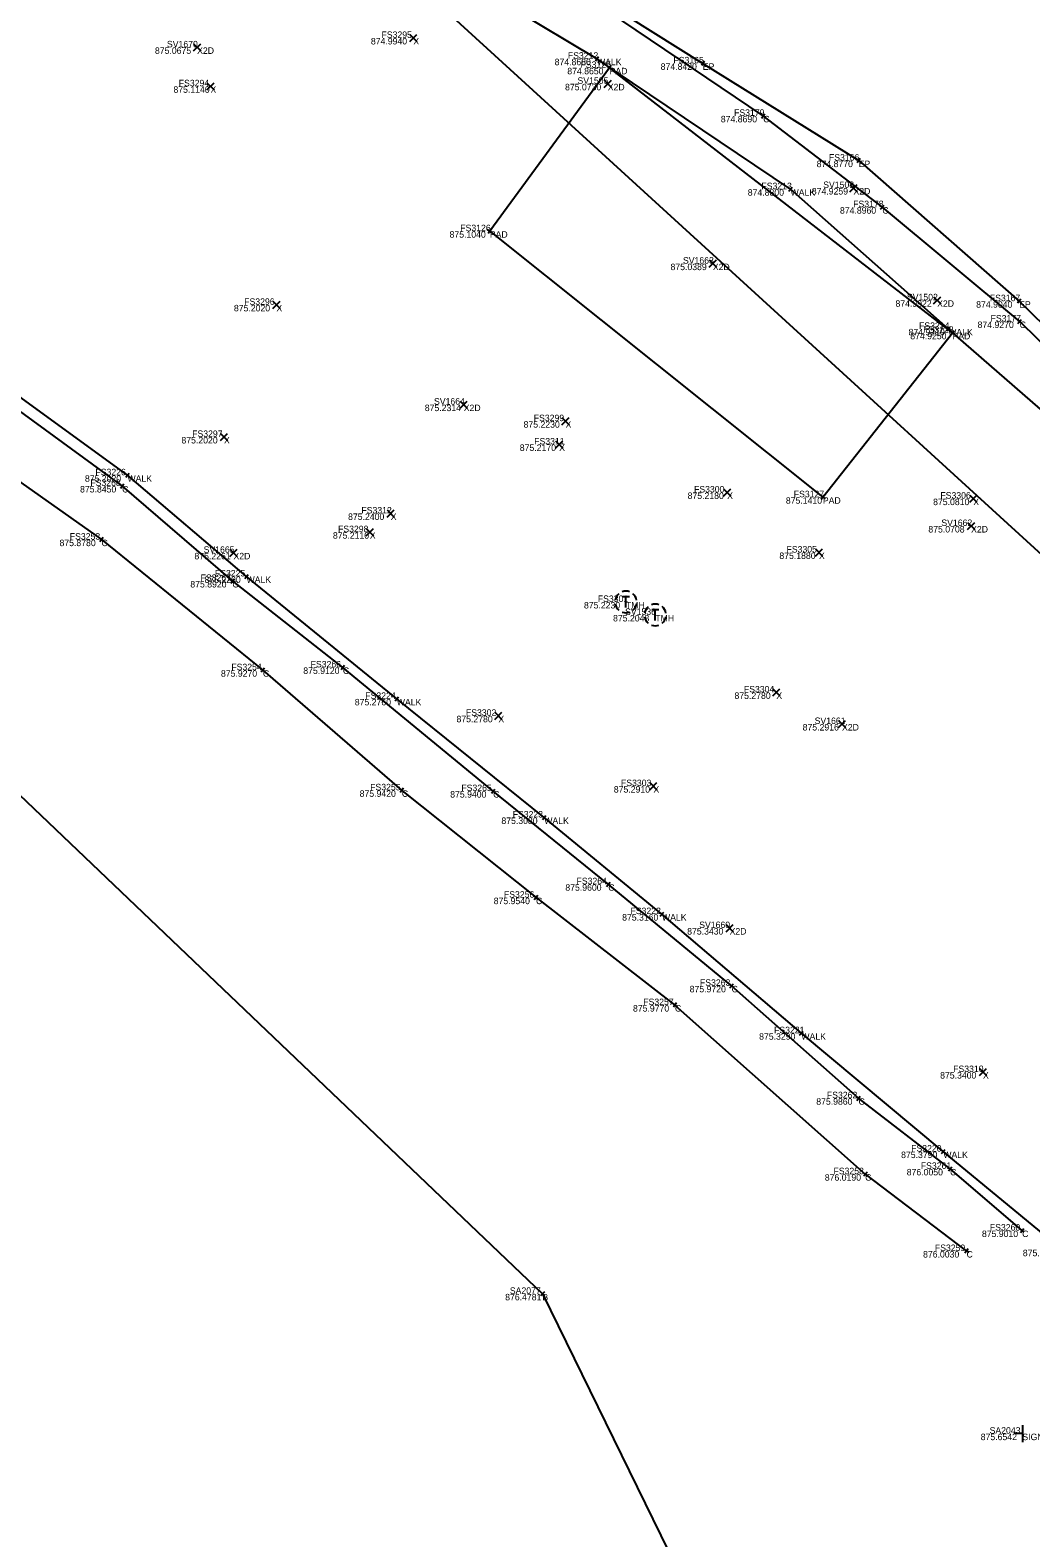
# Model space of a CAD drawing. Extents: x 1479481 to 1575806, y 316056 to 379927.
# Drawn here: x 1480179.92 to 1480189.17, y 379370.17 to 379384.1 of the extents above; entities that cross this region are included whole.
import ezdxf

# ---------------------------------------------------------------- set-up
doc = ezdxf.new("R2010")
doc.units = 0
for name, color, linetype in [('Default', 7, 'Continuous'), ('PV_X_Curb', 7, 'Continuous'), ('PV_X_EOP', 7, 'Continuous'), ('PV_X_Walk', 7, 'Continuous'), ('RD_X_Concrete_Pad', 7, 'Continuous'), ('SN_X_Public', 7, 'Continuous'), ('SV_X_Break_Lines', 7, 'Continuous'), ('SV_X_Random_Point', 7, 'Continuous'), ('SV_X_Shot_Marker', 7, 'Continuous'), ('SV_X_Text_Comment', 7, 'Continuous'), ('SV_X_Text_Elevation', 7, 'Continuous'), ('SV_X_Text_Name', 7, 'Continuous'), ('UT_X_Telecom_Cells', 7, 'Continuous'), ('UT_X_Water', 7, 'Continuous')]:
    doc.layers.add(name, color=color, linetype=linetype)

msp = doc.modelspace()

# ---------------------------------------------------------------- linework, layer by layer
at = {"layer": 'Default'}
msp.add_lwpolyline([(1480189.091, 379371.129), (1480189.091, 379371.129)], dxfattribs=at)
at = {"layer": 'PV_X_Curb'}
for points in [[(1480200.436, 379370.31), (1480193.202, 379376.933), (1480192.331, 379377.692), (1480191.145, 379378.864), (1480189.945, 379379.999), (1480188.405, 379381.34), (1480186.948, 379382.631), (1480185.159, 379383.837), (1480183.612, 379384.764), (1480182.42, 379385.277), (1480180.94, 379385.773), (1480179.383, 379386.306), (1480178.708, 379386.55), (1480176.982, 379386.784), (1480175.084, 379387.087), (1480173.11, 379387.257), (1480172.166, 379387.208), (1480170.557, 379387.026), (1480168.815, 379386.8), (1480167.667, 379386.487), (1480166.614, 379386.24), (1480165.014, 379385.711), (1480163.297, 379385.035), (1480160.165, 379383.332)], [(1480200.731, 379370.664), (1480194.552, 379376.232), (1480193.456, 379377.305), (1480192.298, 379378.387), (1480191.096, 379379.488), (1480190.065, 379380.428), (1480189.066, 379381.408), (1480187.797, 379382.465), (1480186.696, 379383.309), (1480185.265, 379384.273), (1480183.824, 379385.018), (1480182.233, 379385.673), (1480180.762, 379386.381), (1480178.806, 379386.86)], [(1480189.089, 379373.006), (1480188.423, 379373.576), (1480187.577, 379374.229), (1480186.404, 379375.268), (1480185.264, 379376.207), (1480184.2, 379377.068), (1480182.811, 379378.211), (1480181.79, 379379.01), (1480180.771, 379379.888), (1480179.591, 379380.749), (1480178.478, 379381.451), (1480177.363, 379382.074), (1480176.239, 379382.561), (1480175.143, 379382.897), (1480174.151, 379383.12), (1480173.021, 379383.226), (1480171.702, 379383.276), (1480170.402, 379383.235), (1480169.07, 379383.109), (1480167.976, 379382.926), (1480167.142, 379382.859)], [(1480164.924, 379381.791), (1480165.136, 379381.45), (1480165.602, 379381.663), (1480167.13, 379382.362), (1480169.323, 379382.6), (1480170.636, 379382.736), (1480171.845, 379382.75), (1480173.369, 379382.695), (1480174.769, 379382.445), (1480175.791, 379382.176), (1480176.934, 379381.802), (1480177.312, 379381.546), (1480178.119, 379381.083), (1480179.444, 379380.194), (1480180.58, 379379.392), (1480182.072, 379378.185), (1480183.356, 379377.075), (1480184.596, 379376.083), (1480185.88, 379375.09), (1480187.638, 379373.527), (1480188.575, 379372.817)]]:
    msp.add_lwpolyline(points, dxfattribs=at)
at = {"layer": 'PV_X_EOP'}
msp.add_lwpolyline([(1480162.636, 379385.472), (1480163.801, 379386.077), (1480165.418, 379386.485), (1480167.155, 379386.981), (1480168.73, 379387.376), (1480170.459, 379387.707), (1480172.465, 379387.875), (1480174.363, 379387.724), (1480176.285, 379387.6), (1480178.413, 379387.246), (1480180.385, 379386.755), (1480182.516, 379385.858), (1480184.495, 379384.826), (1480186.137, 379383.794), (1480187.578, 379382.895), (1480189.061, 379381.596), (1480190.464, 379380.232), (1480191.921, 379378.963), (1480193.467, 379377.516), (1480195.917, 379375.21)], dxfattribs=at)
at = {"layer": 'PV_X_Walk'}
msp.add_lwpolyline([(1480189.463, 379372.829), (1480188.36, 379373.736), (1480187.048, 379374.83), (1480185.76, 379375.931), (1480184.672, 379376.824), (1480183.309, 379377.92), (1480181.92, 379379.052), (1480180.82, 379379.987), (1480179.405, 379381.013), (1480178.224, 379381.663), (1480176.75, 379382.48), (1480175.258, 379382.991), (1480173.616, 379383.331), (1480171.941, 379383.389), (1480170.042, 379383.312), (1480168.62, 379383.135), (1480167.121, 379382.898), (1480164.933, 379381.864)], dxfattribs=at)
at = {"layer": 'RD_X_Concrete_Pad'}
msp.add_lwpolyline([(1480185.276, 379383.753), (1480184.169, 379382.243), (1480187.247, 379379.784), (1480188.445, 379381.304)], close=True, dxfattribs=at)
at = {"layer": 'SN_X_Public'}
for p, q in [((1480189.091, 379371.209), (1480189.091, 379371.049)), ((1480189.091, 379371.129), (1480189.011, 379371.129))]:
    msp.add_line(p, q, dxfattribs=at)
at = {"layer": 'SV_X_Break_Lines'}
msp.add_lwpolyline([(1480109.136, 379300.654), (1480103.503, 379307.396), (1480120.541, 379324.578), (1480124.787, 379337.805), (1480137.007, 379352.173), (1480144.932, 379357.565), (1480149.611, 379361.971), (1480150.052, 379364.189), (1480148.777, 379365.458), (1480163.875, 379379.601), (1480168.818, 379380.654), (1480172.802, 379381.332), (1480178.472, 379378.317), (1480184.655, 379372.421), (1480187.645, 379366.317)], dxfattribs=at)
at = {"layer": 'SV_X_Random_Point'}
for p, q in [((1480183.429, 379383.996), (1480183.495, 379384.062)), ((1480183.429, 379384.062), (1480183.495, 379383.996)), ((1480181.431, 379383.909), (1480181.497, 379383.976)), ((1480181.431, 379383.976), (1480181.497, 379383.909)), ((1480181.554, 379383.549), (1480181.62, 379383.615)), ((1480181.554, 379383.615), (1480181.62, 379383.549)), ((1480185.226, 379383.571), (1480185.292, 379383.638)), ((1480185.226, 379383.638), (1480185.292, 379383.571)), ((1480187.497, 379382.608), (1480187.563, 379382.675)), ((1480187.497, 379382.675), (1480187.563, 379382.608)), ((1480186.197, 379381.91), (1480186.263, 379381.977)), ((1480186.197, 379381.977), (1480186.263, 379381.91)), ((1480188.27, 379381.571), (1480188.336, 379381.637)), ((1480188.27, 379381.637), (1480188.336, 379381.571)), ((1480182.164, 379381.529), (1480182.23, 379381.595)), ((1480182.164, 379381.595), (1480182.23, 379381.529)), ((1480183.895, 379380.606), (1480183.961, 379380.673)), ((1480183.895, 379380.673), (1480183.961, 379380.606)), ((1480184.836, 379380.454), (1480184.902, 379380.52)), ((1480184.836, 379380.52), (1480184.902, 379380.454)), ((1480181.679, 379380.308), (1480181.745, 379380.374)), ((1480181.679, 379380.374), (1480181.745, 379380.308)), ((1480184.777, 379380.239), (1480184.843, 379380.305)), ((1480184.777, 379380.305), (1480184.843, 379380.239)), ((1480186.329, 379379.795), (1480186.395, 379379.861)), ((1480186.329, 379379.861), (1480186.395, 379379.795)), ((1480188.604, 379379.738), (1480188.67, 379379.804)), ((1480188.604, 379379.804), (1480188.67, 379379.738)), ((1480183.22, 379379.601), (1480183.286, 379379.667)), ((1480183.22, 379379.667), (1480183.286, 379379.601)), ((1480188.584, 379379.485), (1480188.65, 379379.552)), ((1480188.584, 379379.552), (1480188.65, 379379.485)), ((1480183.027, 379379.428), (1480183.093, 379379.494)), ((1480183.027, 379379.494), (1480183.093, 379379.428)), ((1480181.767, 379379.237), (1480181.833, 379379.303)), ((1480181.767, 379379.303), (1480181.833, 379379.237)), ((1480187.178, 379379.24), (1480187.244, 379379.306)), ((1480187.178, 379379.306), (1480187.244, 379379.24)), ((1480186.784, 379377.947), (1480186.85, 379378.013)), ((1480186.784, 379378.013), (1480186.85, 379377.947)), ((1480184.215, 379377.731), (1480184.281, 379377.797)), ((1480184.215, 379377.797), (1480184.281, 379377.731)), ((1480187.391, 379377.655), (1480187.457, 379377.721)), ((1480187.391, 379377.721), (1480187.457, 379377.655)), ((1480185.648, 379377.081), (1480185.714, 379377.147)), ((1480185.648, 379377.147), (1480185.714, 379377.081)), ((1480186.352, 379375.768), (1480186.418, 379375.835)), ((1480186.352, 379375.835), (1480186.418, 379375.768)), ((1480188.694, 379374.438), (1480188.76, 379374.504)), ((1480188.694, 379374.504), (1480188.76, 379374.438))]:
    msp.add_line(p, q, dxfattribs=at)
at = {"layer": 'SV_X_Shot_Marker'}
for p, q in [((1480185.18, 379383.823), (1480185.138, 379383.851)), ((1480185.145, 379383.816), (1480185.173, 379383.858)), ((1480185.159, 379383.837), (1480185.159, 379383.837)), ((1480185.296, 379383.738), (1480185.256, 379383.768)), ((1480185.291, 379383.773), (1480185.261, 379383.733)), ((1480185.276, 379383.753), (1480185.276, 379383.753)), ((1480186.116, 379383.807), (1480186.158, 379383.781)), ((1480186.15, 379383.815), (1480186.124, 379383.773)), ((1480186.137, 379383.794), (1480186.137, 379383.794)), ((1480186.716, 379383.294), (1480186.676, 379383.324)), ((1480186.681, 379383.289), (1480186.711, 379383.329)), ((1480186.696, 379383.309), (1480186.696, 379383.309)), ((1480187.557, 379382.908), (1480187.599, 379382.882)), ((1480187.591, 379382.916), (1480187.565, 379382.874)), ((1480187.578, 379382.895), (1480187.578, 379382.895)), ((1480186.967, 379382.614), (1480186.929, 379382.648)), ((1480186.931, 379382.612), (1480186.965, 379382.65)), ((1480186.948, 379382.631), (1480186.948, 379382.631)), ((1480187.816, 379382.449), (1480187.778, 379382.481)), ((1480187.781, 379382.446), (1480187.813, 379382.485)), ((1480187.797, 379382.465), (1480187.797, 379382.465)), ((1480184.189, 379382.228), (1480184.149, 379382.258)), ((1480184.184, 379382.263), (1480184.154, 379382.223)), ((1480184.169, 379382.243), (1480184.169, 379382.243)), ((1480189.042, 379381.612), (1480189.08, 379381.58)), ((1480189.077, 379381.615), (1480189.045, 379381.577)), ((1480189.061, 379381.596), (1480189.061, 379381.596)), ((1480188.424, 379381.324), (1480188.386, 379381.356)), ((1480188.389, 379381.321), (1480188.421, 379381.359)), ((1480189.048, 379381.39), (1480189.084, 379381.426)), ((1480189.084, 379381.391), (1480189.048, 379381.426)), ((1480189.066, 379381.408), (1480189.066, 379381.408)), ((1480188.405, 379381.34), (1480188.405, 379381.34)), ((1480188.425, 379381.319), (1480188.465, 379381.289)), ((1480188.43, 379381.284), (1480188.46, 379381.324)), ((1480188.445, 379381.304), (1480188.445, 379381.304)), ((1480180.839, 379379.971), (1480180.801, 379380.003)), ((1480180.804, 379379.968), (1480180.836, 379380.006)), ((1480180.82, 379379.987), (1480180.82, 379379.987)), ((1480180.79, 379379.871), (1480180.752, 379379.904)), ((1480180.755, 379379.869), (1480180.788, 379379.907)), ((1480180.771, 379379.888), (1480180.771, 379379.888)), ((1480187.227, 379379.8), (1480187.267, 379379.768)), ((1480187.263, 379379.804), (1480187.231, 379379.764)), ((1480187.247, 379379.784), (1480187.247, 379379.784)), ((1480180.56, 379379.406), (1480180.6, 379379.378)), ((1480180.594, 379379.412), (1480180.566, 379379.372)), ((1480180.58, 379379.392), (1480180.58, 379379.392)), ((1480181.81, 379378.994), (1480181.77, 379379.025)), ((1480181.774, 379378.99), (1480181.805, 379379.03)), ((1480181.79, 379379.01), (1480181.79, 379379.01)), ((1480181.939, 379379.036), (1480181.901, 379379.068)), ((1480181.904, 379379.033), (1480181.936, 379379.071)), ((1480181.92, 379379.052), (1480181.92, 379379.052)), ((1480182.053, 379378.201), (1480182.091, 379378.169)), ((1480182.088, 379378.204), (1480182.056, 379378.166)), ((1480182.072, 379378.185), (1480182.072, 379378.185)), ((1480182.83, 379378.195), (1480182.791, 379378.227)), ((1480182.795, 379378.192), (1480182.827, 379378.231)), ((1480182.811, 379378.211), (1480182.811, 379378.211)), ((1480183.328, 379377.904), (1480183.29, 379377.936)), ((1480183.293, 379377.901), (1480183.325, 379377.939)), ((1480183.309, 379377.92), (1480183.309, 379377.92)), ((1480183.337, 379377.091), (1480183.375, 379377.059)), ((1480183.372, 379377.094), (1480183.34, 379377.056)), ((1480183.356, 379377.075), (1480183.356, 379377.075)), ((1480184.219, 379377.052), (1480184.18, 379377.084)), ((1480184.184, 379377.048), (1480184.216, 379377.087)), ((1480184.2, 379377.068), (1480184.2, 379377.068)), ((1480184.691, 379376.808), (1480184.653, 379376.84)), ((1480184.656, 379376.805), (1480184.688, 379376.843)), ((1480184.672, 379376.824), (1480184.672, 379376.824)), ((1480185.283, 379376.191), (1480185.244, 379376.222)), ((1480185.248, 379376.187), (1480185.28, 379376.226)), ((1480185.264, 379376.207), (1480185.264, 379376.207)), ((1480184.576, 379376.099), (1480184.616, 379376.067)), ((1480184.612, 379376.103), (1480184.58, 379376.063)), ((1480184.596, 379376.083), (1480184.596, 379376.083)), ((1480185.779, 379375.915), (1480185.741, 379375.947)), ((1480185.744, 379375.912), (1480185.776, 379375.95)), ((1480185.76, 379375.931), (1480185.76, 379375.931)), ((1480186.423, 379375.251), (1480186.386, 379375.284)), ((1480186.388, 379375.249), (1480186.421, 379375.286)), ((1480186.404, 379375.268), (1480186.404, 379375.268)), ((1480185.86, 379375.105), (1480185.9, 379375.075)), ((1480185.895, 379375.11), (1480185.865, 379375.07)), ((1480185.88, 379375.09), (1480185.88, 379375.09)), ((1480187.067, 379374.814), (1480187.029, 379374.846)), ((1480187.032, 379374.811), (1480187.064, 379374.849)), ((1480187.048, 379374.83), (1480187.048, 379374.83)), ((1480187.597, 379374.214), (1480187.557, 379374.244)), ((1480187.562, 379374.209), (1480187.592, 379374.249)), ((1480187.577, 379374.229), (1480187.577, 379374.229)), ((1480188.379, 379373.72), (1480188.341, 379373.752)), ((1480188.344, 379373.717), (1480188.376, 379373.755)), ((1480188.36, 379373.736), (1480188.36, 379373.736)), ((1480187.619, 379373.544), (1480187.657, 379373.51)), ((1480187.655, 379373.546), (1480187.621, 379373.508)), ((1480188.442, 379373.559), (1480188.404, 379373.592)), ((1480188.407, 379373.557), (1480188.439, 379373.595)), ((1480188.423, 379373.576), (1480188.423, 379373.576)), ((1480187.638, 379373.527), (1480187.638, 379373.527)), ((1480189.108, 379372.99), (1480189.07, 379373.022)), ((1480189.073, 379372.987), (1480189.105, 379373.025)), ((1480189.089, 379373.006), (1480189.089, 379373.006)), ((1480188.555, 379372.832), (1480188.595, 379372.802)), ((1480188.59, 379372.837), (1480188.56, 379372.797)), ((1480188.575, 379372.817), (1480188.575, 379372.817)), ((1480184.637, 379372.439), (1480184.673, 379372.404)), ((1480184.673, 379372.439), (1480184.638, 379372.403)), ((1480184.655, 379372.421), (1480184.655, 379372.421))]:
    msp.add_line(p, q, dxfattribs=at)
at = {"layer": 'UT_X_Telecom_Cells'}
for p, q in [((1480185.395, 379378.866), (1480185.46, 379378.866)), ((1480185.427, 379378.766), (1480185.427, 379378.866)), ((1480185.427, 379378.816), (1480185.427, 379378.816)), ((1480185.666, 379378.746), (1480185.731, 379378.746)), ((1480185.698, 379378.646), (1480185.698, 379378.746)), ((1480185.698, 379378.696), (1480185.698, 379378.696))]:
    msp.add_line(p, q, dxfattribs=at)
for centre, start, end in [((1480185.427, 379378.816), 130.0806, 170.0721), ((1480185.427, 379378.816), 70.0577, 110.1061), ((1480185.427, 379378.816), 10.0169, 50.0392), ((1480185.427, 379378.816), 190.0169, 230.0392), ((1480185.427, 379378.816), 250.0577, 290.0473), ((1480185.427, 379378.816), 310.0114, 350.0264), ((1480185.698, 379378.696), 130.0806, 170.0721), ((1480185.698, 379378.696), 70.0577, 110.1061), ((1480185.698, 379378.696), 10.0169, 50.0392), ((1480185.698, 379378.696), 190.0169, 230.0392), ((1480185.698, 379378.696), 250.0577, 290.0473), ((1480185.698, 379378.696), 310.0114, 350.0264)]:
    msp.add_arc(centre, 0.1, start, end, dxfattribs=at)
at = {"layer": 'UT_X_Water'}
msp.add_lwpolyline([(1480234.677, 379335.863), (1480225.088, 379345.601), (1480208.322, 379361.342), (1480207.346, 379362.25), (1480199.528, 379369.768), (1480193.21, 379375.651), (1480182.823, 379385.139), (1480177.927, 379389.525), (1480169.423, 379398.321), (1480161.035, 379406.189), (1480144.924, 379421.019), (1480134.739, 379430.559), (1480121.485, 379441.998), (1480113.085, 379450.369), (1480106.418, 379456.915), (1480094.539, 379467.985), (1480089.15, 379472.551), (1480086.751, 379474.713), (1480073.459, 379487.337), (1480068.123, 379493.187), (1480050.678, 379510.207), (1480044.404, 379515.873)], dxfattribs=at)

# ---------------------------------------------------------------- texts
at = {"layer": 'SV_X_Text_Comment'}
for s, p in [('X', (1480183.462, 379383.969)), ('X2D', (1480181.464, 379383.882)), ('WALK', (1480185.159, 379383.777)), ('PAD', (1480185.276, 379383.693)), ('EP', (1480186.137, 379383.734)), ('X', (1480181.587, 379383.522)), ('X2D', (1480185.259, 379383.545)), ('C', (1480186.696, 379383.249)), ('EP', (1480187.578, 379382.835)), ('WALK', (1480186.948, 379382.571)), ('X2D', (1480187.53, 379382.582)), ('C', (1480187.797, 379382.405)), ('PAD', (1480184.169, 379382.183)), ('X2D', (1480186.23, 379381.883)), ('X', (1480182.197, 379381.502)), ('X2D', (1480188.303, 379381.544)), ('EP', (1480189.061, 379381.536)), ('C', (1480189.066, 379381.348)), ('WALK', (1480188.405, 379381.28)), ('PAD', (1480188.445, 379381.244)), ('X2D', (1480183.928, 379380.58)), ('X', (1480184.869, 379380.427)), ('X', (1480181.712, 379380.281)), ('X', (1480184.81, 379380.212)), ('WALK', (1480180.82, 379379.927)), ('C', (1480180.771, 379379.828)), ('X', (1480186.362, 379379.768)), ('PAD', (1480187.247, 379379.724)), ('X', (1480188.637, 379379.711)), ('X', (1480183.253, 379379.574)), ('C', (1480180.58, 379379.332)), ('X', (1480183.06, 379379.401)), ('X2D', (1480188.617, 379379.458)), ('X2D', (1480181.8, 379379.21)), ('X', (1480187.211, 379379.213)), ('C', (1480181.79, 379378.95)), ('WALK', (1480181.92, 379378.992)), ('TMH', (1480185.427, 379378.756)), ('TMH', (1480185.698, 379378.636)), ('C', (1480182.072, 379378.125)), ('C', (1480182.811, 379378.151)), ('WALK', (1480183.309, 379377.86)), ('X', (1480186.817, 379377.92)), ('X', (1480184.248, 379377.704)), ('X2D', (1480187.424, 379377.628)), ('C', (1480183.356, 379377.015)), ('C', (1480184.2, 379377.008)), ('X', (1480185.681, 379377.054)), ('WALK', (1480184.672, 379376.764)), ('C', (1480185.264, 379376.147)), ('C', (1480184.596, 379376.023)), ('WALK', (1480185.76, 379375.871)), ('X2D', (1480186.385, 379375.742)), ('C', (1480186.404, 379375.208)), ('C', (1480185.88, 379375.03)), ('WALK', (1480187.048, 379374.77)), ('X', (1480188.727, 379374.411)), ('C', (1480187.577, 379374.169)), ('WALK', (1480188.36, 379373.676)), ('C', (1480188.423, 379373.516)), ('C', (1480187.638, 379373.467)), ('C', (1480189.089, 379372.946)), ('C', (1480188.575, 379372.757)), ('B', (1480184.655, 379372.361)), ('SIGNPB', (1480189.091, 379371.069))]:
    msp.add_text(s, height=0.06, dxfattribs=at).set_placement(p)
at = {"layer": 'SV_X_Text_Elevation'}
for s, p in [('874.9940', (1480183.07, 379383.969)), ('875.0675', (1480181.074, 379383.882)), ('874.8680', (1480184.768, 379383.777)), ('874.8650', (1480184.885, 379383.693)), ('874.8420', (1480185.748, 379383.734)), ('875.1140', (1480181.245, 379383.522)), ('875.0730', (1480184.864, 379383.545)), ('874.8690', (1480186.304, 379383.249)), ('874.8770', (1480187.19, 379382.835)), ('874.8800', (1480186.553, 379382.571)), ('874.9259', (1480187.145, 379382.582)), ('874.8960', (1480187.405, 379382.405)), ('875.1040', (1480183.797, 379382.183)), ('875.0389', (1480185.839, 379381.883)), ('875.2020', (1480181.804, 379381.502)), ('874.9922', (1480187.918, 379381.544)), ('874.9040', (1480188.664, 379381.536)), ('874.9210', (1480188.039, 379381.28)), ('874.9270', (1480188.677, 379381.348)), ('874.9250', (1480188.055, 379381.244)), ('875.2314', (1480183.568, 379380.58)), ('875.2230', (1480184.481, 379380.427)), ('875.2020', (1480181.319, 379380.281)), ('875.2170', (1480184.446, 379380.212)), ('875.2020', (1480180.427, 379379.927)), ('875.8450', (1480180.382, 379379.828)), ('875.2180', (1480185.997, 379379.768)), ('875.1410', (1480186.905, 379379.724)), ('875.0810', (1480188.266, 379379.711)), ('875.2400', (1480182.859, 379379.574)), ('875.8780', (1480180.192, 379379.332)), ('875.2110', (1480182.719, 379379.401)), ('875.0708', (1480188.222, 379379.458)), ('875.2261', (1480181.439, 379379.21)), ('875.1880', (1480186.845, 379379.213)), ('875.8920', (1480181.401, 379378.95)), ('875.2290', (1480181.532, 379378.992)), ('875.2230', (1480185.039, 379378.756)), ('875.2048', (1480185.308, 379378.636)), ('875.9270', (1480181.684, 379378.125)), ('875.9120', (1480182.445, 379378.151)), ('875.2760', (1480182.921, 379377.86)), ('875.2780', (1480186.43, 379377.92)), ('875.2780', (1480183.861, 379377.704)), ('875.2916', (1480187.06, 379377.628)), ('875.9420', (1480182.966, 379377.015)), ('875.9400', (1480183.803, 379377.008)), ('875.2910', (1480185.315, 379377.054)), ('875.3080', (1480184.276, 379376.764)), ('875.9600', (1480184.867, 379376.147)), ('875.9540', (1480184.205, 379376.023)), ('875.3160', (1480185.392, 379375.871)), ('875.3430', (1480185.993, 379375.742)), ('875.9720', (1480186.016, 379375.208)), ('875.9770', (1480185.492, 379375.03)), ('875.3290', (1480186.658, 379374.77)), ('875.3400', (1480188.331, 379374.411)), ('875.9860', (1480187.186, 379374.169)), ('875.3790', (1480187.97, 379373.676)), ('876.0050', (1480188.022, 379373.516)), ('876.0190', (1480187.265, 379373.467)), ('875.9010', (1480188.717, 379372.946)), ('876.0030', (1480188.173, 379372.757)), ('875.3610', (1480189.095, 379372.769)), ('876.4781', (1480184.311, 379372.361)), ('875.6542', (1480188.706, 379371.069))]:
    msp.add_text(s, height=0.06, dxfattribs=at).set_placement(p)
at = {"layer": 'SV_X_Text_Name'}
for s, p in [('SV1670', (1480181.185, 379383.942)), ('FS3295', (1480183.168, 379384.029)), ('FS3212', (1480184.89, 379383.837)), ('FS3165', (1480185.866, 379383.794)), ('FS3125', (1480185.007, 379383.753)), ('FS3294', (1480181.294, 379383.582)), ('SV1505', (1480184.979, 379383.605)), ('FS3179', (1480186.426, 379383.309)), ('FS3166', (1480187.303, 379382.895)), ('FS3213', (1480186.679, 379382.631)), ('SV1503', (1480187.25, 379382.642)), ('FS3178', (1480187.527, 379382.465)), ('FS3126', (1480183.896, 379382.243)), ('SV1663', (1480185.954, 379381.943)), ('FS3296', (1480181.899, 379381.562)), ('SV1502', (1480188.024, 379381.604)), ('FS3167', (1480188.79, 379381.596)), ('FS3214', (1480188.136, 379381.34)), ('FS3128', (1480188.175, 379381.304)), ('FS3177', (1480188.797, 379381.408)), ('SV1664', (1480183.653, 379380.64)), ('FS3299', (1480184.575, 379380.487)), ('FS3297', (1480181.418, 379380.341)), ('FS3311', (1480184.579, 379380.272)), ('FS3268', (1480180.477, 379379.888)), ('FS3226', (1480180.524, 379379.987)), ('FS3300', (1480186.056, 379379.828)), ('FS3127', (1480186.978, 379379.784)), ('FS3306', (1480188.333, 379379.771)), ('FS3312', (1480182.982, 379379.634)), ('SV1662', (1480188.342, 379379.518)), ('FS3253', (1480180.287, 379379.392)), ('FS3298', (1480182.766, 379379.461)), ('SV1665', (1480181.524, 379379.27)), ('FS3305', (1480186.911, 379379.273)), ('FS3225', (1480181.628, 379379.052)), ('FS3267', (1480181.496, 379379.01)), ('FS3301', (1480185.167, 379378.816)), ('SV1536', (1480185.419, 379378.696)), ('FS3254', (1480181.78, 379378.185)), ('FS3266', (1480182.513, 379378.211)), ('FS3304', (1480186.517, 379377.98)), ('FS3224', (1480183.018, 379377.92)), ('FS3302', (1480183.948, 379377.764)), ('SV1661', (1480187.171, 379377.688)), ('FS3303', (1480185.381, 379377.114)), ('FS3255', (1480183.063, 379377.075)), ('FS3265', (1480183.906, 379377.068)), ('FS3223', (1480184.38, 379376.824)), ('FS3264', (1480184.97, 379376.207)), ('FS3256', (1480184.299, 379376.083)), ('FS3222', (1480185.469, 379375.931)), ('SV1660', (1480186.104, 379375.802)), ('FS3263', (1480186.111, 379375.268)), ('FS3257', (1480185.587, 379375.09)), ('FS3221', (1480186.796, 379374.83)), ('FS3310', (1480188.451, 379374.471)), ('FS3262', (1480187.284, 379374.229)), ('FS3220', (1480188.063, 379373.736)), ('FS3258', (1480187.345, 379373.527)), ('FS3261', (1480188.152, 379373.576)), ('FS3260', (1480188.79, 379373.006)), ('FS3259', (1480188.282, 379372.817)), ('SA2077', (1480184.354, 379372.421)), ('SA2043', (1480188.788, 379371.129))]:
    msp.add_text(s, height=0.06, dxfattribs=at).set_placement(p)

doc.saveas('drawing.dxf')
